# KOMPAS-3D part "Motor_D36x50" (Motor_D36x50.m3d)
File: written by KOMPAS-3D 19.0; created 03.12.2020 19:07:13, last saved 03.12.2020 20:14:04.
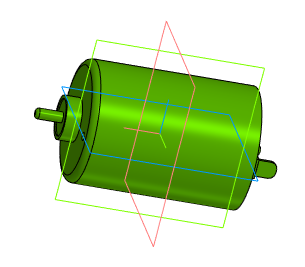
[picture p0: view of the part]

Document properties: Автор: Agent Smith; Полное имя файла: D:\3D_print\3D проекты Компас 3D\Халява Projects_3\Motor_D36x50.m3d

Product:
- Part/product: Motor_D36x50
    Масса: 0.403081

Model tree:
1. Эскиз:1
2. Элемент выдавливания:1
     Расстояние 1 = 50
3. Эскиз:2  (with: Элемент выдавливания:1)
4. Элемент выдавливания:2
     Расстояние 1 = 4.6
5. Эскиз:3  (with: Элемент выдавливания:2)
6. Элемент выдавливания:3
     Расстояние 2 = 0.4
7. Скругление:1  (with: Элемент выдавливания:1)
     Радиус = 2
8. Эскиз:4  (with: Элемент выдавливания:3)
9. Элемент выдавливания:4
     Расстояние 1 = 8
10. Скругление:2  (with: Элемент выдавливания:4)
     Радиус = 1
11. Эскиз:5  (with: Элемент выдавливания:1, Скругление:1)
12. Элемент выдавливания:5
     Расстояние 2 = 10
13. Эскиз:6  (with: Элемент выдавливания:1)
14. Элемент выдавливания:6
     Расстояние 2 = 0.8
15. Скругление:3  (with: Элемент выдавливания:6)
     Радиус = 0.6
16. Эскиз:7  (with: Элемент выдавливания:1, Скругление:3)
17. Элемент выдавливания:7
     Расстояние 1 = 3
18. Эскиз:8  (with: Элемент выдавливания:7)
19. Элемент выдавливания:8
     Расстояние 2 = 0.4
20. Эскиз:9  (with: Элемент выдавливания:8)
21. Элемент выдавливания:9
     Расстояние 1 = 2.2
22. Скругление:4  (with: Элемент выдавливания:9)
     Радиус = 1
23. Эскиз:10  (with: Элемент выдавливания:6)
24. Элемент выдавливания:10
     Расстояние 1 = 2
25. Эскиз:11  (with: Элемент выдавливания:10)
26. Элемент выдавливания:11
     Расстояние 1 = 6
27. Скругление:5  (with: Элемент выдавливания:11)
     Радиус = 2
